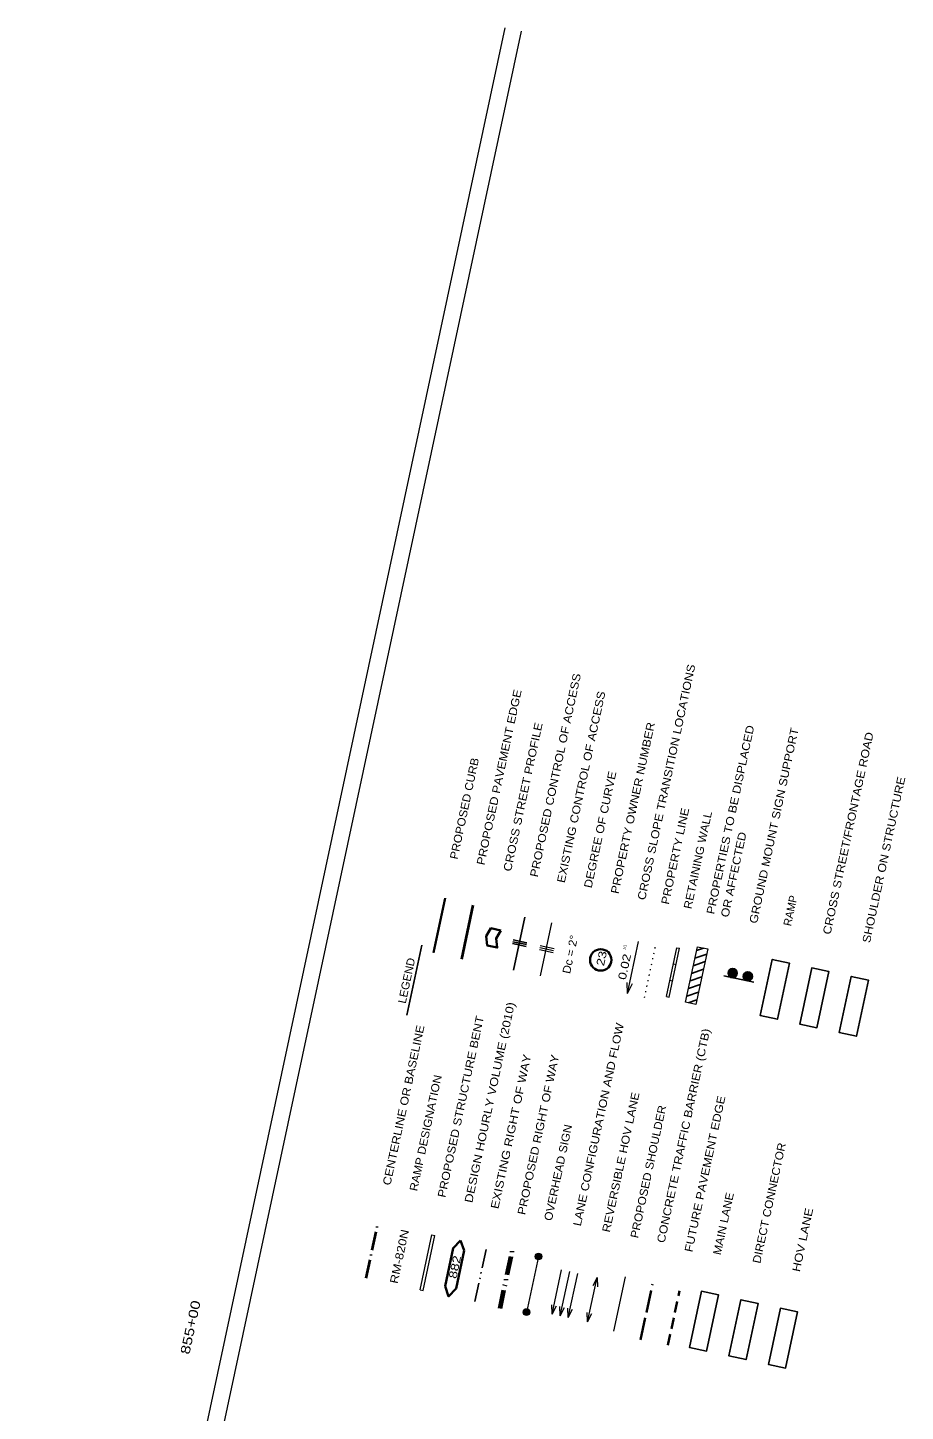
# Model space of a CAD drawing. Extents: x 2363411 to 2369702, y 6977197 to 6988655.
# Drawn here: x 2368386 to 2369702, y 6985397 to 6987471 of the extents above; entities that cross this region are included whole.
import ezdxf
from ezdxf.enums import TextEntityAlignment as Align

# ---------------------------------------------------------------- set-up
doc = ezdxf.new("R2010")
doc.units = 0
doc.header["$LTSCALE"] = 5.6
for name, pattern in [('DASH_DOUBLE_DOT', [9.2, 5, -1.2, 0.3, -1.2, 0.3, -1.2]), ('DOT_DASHED', [7.7, 5, -1.2, 0.3, -1.2]), ('DOTTED', [1.5, 0.3, -1.2]), ('LONG_DASHED', [7.5, 6, -1.5]), ('MEDIUM_DASHED', [4.5, 3, -1.5])]:
    doc.linetypes.add(name, pattern=pattern)
for name, color, linetype, lineweight in [('10', 7, 'Continuous', 13), ('2', 7, 'LONG_DASHED', 35), ('3', 7, 'Continuous', 13), ('44', 7, 'Continuous', 25), ('62', 7, 'Continuous', 25), ('7', 7, 'Continuous', 25)]:
    doc.layers.add(name, color=color, linetype=linetype, lineweight=lineweight)

msp = doc.modelspace()

# ---------------------------------------------------------------- hatches: boundary and pattern name
at = {"layer": '3'}
for points in [[(2369444.466, 6986060.545, 1), (2369441.566, 6986046.971, 1)], [(2369467.219, 6986055.682, 1), (2369464.319, 6986042.109, 1)], [(2369152.887, 6985633.803, 1), (2369150.797, 6985624.023, 1)], [(2369134.988, 6985550.401, 1), (2369132.898, 6985540.621, 1)]]:
    msp.add_hatch(color=256, dxfattribs=at).paths.add_polyline_path(points)

# ---------------------------------------------------------------- linework, layer by layer
at = {"layer": '10'}
for p, q in [((2366907.66, 6977202.711), (2369101.754, 6987471.397)), ((2366932.108, 6977197.487), (2369126.202, 6987466.173))]:
    msp.add_line(p, q, dxfattribs=at)
at = {"layer": '2'}
msp.add_line((2369304.647, 6985503.886), (2369322.798, 6985587.217), dxfattribs=at)
at = {"layer": '3'}
for p, q in [((2368993.928, 6986084.651), (2369011.385, 6986166.351)), ((2368995.395, 6986084.338), (2369012.852, 6986166.037)), ((2369011.224, 6986165.598), (2369011.065, 6986164.855)), ((2369155.018, 6986049.597), (2369171.992, 6986129.038)), ((2369153.188, 6986089.226), (2369173.89, 6986084.803)), ((2369153.815, 6986092.16), (2369174.517, 6986087.737)), ((2369154.441, 6986095.094), (2369175.144, 6986090.671)), ((2369285.259, 6986023.088), (2369301.964, 6986101.267)), ((2369343.667, 6986018.533), (2369359.311, 6986091.885)), ((2369347.588, 6986017.695), (2369363.235, 6986091.047)), ((2369359.327, 6986091.882), (2369363.251, 6986091.046)), ((2369354.113, 6986067.432), (2369358.034, 6986066.594)), ((2369348.895, 6986042.98), (2369352.817, 6986042.144)), ((2369285.259, 6986023.088), (2369284.606, 6986039.65)), ((2369285.259, 6986023.088), (2369292.625, 6986037.937)), ((2369343.678, 6986018.529), (2369347.6, 6986017.693)), ((2368974.484, 6985578.751), (2368992.1, 6985661.194)), ((2368978.983, 6985577.789), (2368996.598, 6985660.233)), ((2368992.1, 6985661.194), (2368996.598, 6985660.233)), ((2369151.843, 6985628.913), (2369133.905, 6985544.963)), ((2369172.363, 6985542.24), (2369186.562, 6985608.692)), ((2369184.413, 6985539.665), (2369198.612, 6985606.117)), ((2369196.461, 6985537.091), (2369210.66, 6985603.543)), ((2369239.737, 6985597.33), (2369240.288, 6985583.254)), ((2369264.741, 6985516.638), (2369282.197, 6985598.338)), ((2368974.484, 6985578.751), (2368978.983, 6985577.789)), ((2369172.363, 6985542.24), (2369171.812, 6985556.315)), ((2369172.363, 6985542.24), (2369178.618, 6985554.861)), ((2369184.413, 6985539.665), (2369183.862, 6985553.741)), ((2369184.413, 6985539.665), (2369190.668, 6985552.286)), ((2369196.461, 6985537.091), (2369195.91, 6985551.166)), ((2369196.461, 6985537.091), (2369202.717, 6985549.712)), ((2369225.539, 6985530.878), (2369224.988, 6985544.953)), ((2369225.539, 6985530.878), (2369231.794, 6985543.499))]:
    msp.add_line(p, q, dxfattribs=at)
at = {"layer": '3', "lineweight": 40}
msp.add_line((2369053.568, 6986155.773), (2369036.272, 6986074.826), dxfattribs=at)
at = {"layer": '3', "lineweight": 25}
for p, q in [((2369114.459, 6986058.263), (2369131.433, 6986137.704)), ((2369113.883, 6986103.76), (2369134.586, 6986099.337)), ((2368954.477, 6985990.905), (2368976.84, 6986095.567)), ((2369112.629, 6986097.893), (2369133.332, 6986093.469)), ((2369113.256, 6986100.826), (2369133.959, 6986096.403)), ((2369429.96, 6986049.577), (2369474.988, 6986039.956))]:
    msp.add_line(p, q, dxfattribs=at)
at = {"layer": '3', "linetype": 'DOTTED'}
msp.add_line((2369310.841, 6986016.937), (2369328.297, 6986098.637), dxfattribs=at)
at = {"layer": '3', "linetype": 'DOT_DASHED', "lineweight": 40}
msp.add_line((2368893.398, 6985596.199), (2368911.028, 6985678.71), dxfattribs=at)
at = {"layer": '3', "lineweight": 35}
for p, q in [((2369040.317, 6985637.557), (2369035.017, 6985652.811)), ((2369028.143, 6985580.581), (2369040.317, 6985637.557))]:
    msp.add_line(p, q, dxfattribs=at)
at = {"layer": '3', "linetype": 'DASH_DOUBLE_DOT', "lineweight": 25}
msp.add_line((2369056.542, 6985561.34), (2369074.172, 6985643.852), dxfattribs=at)
at = {"layer": '3', "linetype": 'DASH_DOUBLE_DOT', "lineweight": 70}
msp.add_line((2369094.114, 6985550.96), (2369113.14, 6985640.004), dxfattribs=at)
at = {"layer": '3', "linetype": 'MEDIUM_DASHED', "lineweight": 35}
msp.add_line((2369345.982, 6985495.732), (2369363.438, 6985577.432), dxfattribs=at)
at = {"layer": '3', "lineweight": 35}
msp.add_lwpolyline([(2369095.512, 6986117.707), (2369088.32, 6986105.776), (2369090.01, 6986091.956), (2369075.086, 6986095.145), (2369073.397, 6986108.965), (2369080.588, 6986120.895)], close=True, dxfattribs=at)
for points in [[(2369011.645, 6985584.106), (2369023.819, 6985641.082), (2369035.017, 6985652.811)], [(2369011.645, 6985584.106), (2369017.08, 6985568.862), (2369028.143, 6985580.581)]]:
    msp.add_lwpolyline(points, dxfattribs=at)
at = {"layer": '3'}
msp.add_lwpolyline([(2369225.539, 6985530.878), (2369239.737, 6985597.33), (2369233.482, 6985584.708)], dxfattribs=at)
at = {"layer": '3', "lineweight": 35}
msp.add_circle((2369245.233, 6986073.549), 16.098, dxfattribs=at)
at = {"layer": '3', "lineweight": 25}
for centre in [(2369443.016, 6986053.758), (2369465.769, 6986048.895)]:
    msp.add_circle(centre, 6.94, dxfattribs=at)
at = {"layer": '3'}
for centre in [(2369151.842, 6985628.913), (2369133.943, 6985545.511)]:
    msp.add_circle(centre, 5, dxfattribs=at)
at = {"layer": '62'}
for points in [[(2369484.449, 6985989.992), (2369502.442, 6986074.202), (2369528.183, 6986068.702), (2369510.19, 6985984.492)], [(2369510.19, 6985984.492), (2369528.183, 6986068.702), (2369502.442, 6986074.202), (2369484.449, 6985989.992)], [(2369543.686, 6985977.335), (2369561.679, 6986061.544), (2369587.418, 6986056.045), (2369569.425, 6985971.836)], [(2369569.425, 6985971.836), (2369587.418, 6986056.045), (2369561.679, 6986061.544), (2369543.686, 6985977.335)], [(2369602.921, 6985964.679), (2369620.914, 6986048.888), (2369646.655, 6986043.388), (2369628.662, 6985959.179)], [(2369628.662, 6985959.179), (2369646.655, 6986043.388), (2369620.914, 6986048.888), (2369602.921, 6985964.679)], [(2369378.131, 6985492.41), (2369396.124, 6985576.619), (2369421.865, 6985571.119), (2369403.872, 6985486.91)], [(2369403.872, 6985486.91), (2369421.865, 6985571.119), (2369396.124, 6985576.619), (2369378.131, 6985492.41)], [(2369437.368, 6985479.753), (2369455.361, 6985563.962), (2369481.1, 6985558.462), (2369463.107, 6985474.253)], [(2369463.107, 6985474.253), (2369481.1, 6985558.462), (2369455.361, 6985563.962), (2369437.368, 6985479.753)], [(2369496.603, 6985467.096), (2369514.596, 6985551.305), (2369540.337, 6985545.805), (2369522.344, 6985461.596)], [(2369522.344, 6985461.596), (2369540.337, 6985545.805), (2369514.596, 6985551.305), (2369496.603, 6985467.096)]]:
    msp.add_lwpolyline(points, close=True, dxfattribs=at)
at = {"layer": '7'}
for p, q in [((2369386.437, 6986076.24), (2369404.094, 6986082.38)), ((2369388.877, 6986087.677), (2369399.413, 6986091.34)), ((2369383.995, 6986064.804), (2369401.652, 6986070.944)), ((2369379.112, 6986041.931), (2369396.767, 6986048.07)), ((2369381.554, 6986053.365), (2369399.208, 6986059.506)), ((2369374.231, 6986019.058), (2369391.883, 6986025.195)), ((2369376.673, 6986030.494), (2369394.325, 6986036.633)), ((2369376.157, 6986009.139), (2369389.442, 6986013.759))]:
    msp.add_line(p, q, dxfattribs=at)
at = {"layer": '7', "lineweight": 13}
msp.add_lwpolyline([(2369387.919, 6986006.63), (2369372.29, 6986009.965), (2369390.085, 6986093.331), (2369405.718, 6986089.993)], close=True, dxfattribs=at)

# ---------------------------------------------------------------- texts
at = {"layer": '3'}
for s, width, p in [('PROPOSED CONTROL OF ACCESS', 1.15, (2369150.538, 6986196.87)), ('CROSS SLOPE TRANSITION LOCATIONS', 1.15, (2369311.807, 6986162.412)), ('PROPOSED PAVEMENT EDGE', 1.15, (2369070.573, 6986214.877)), ('EXISTING CONTROL OF ACCESS', 1.15, (2369191.096, 6986188.204)), ('CROSS STREET PROFILE', 1.15, (2369110.629, 6986205.398)), ('PROPERTY OWNER NUMBER', 1.15, (2369271.749, 6986171.83)), ('PROPERTIES TO BE DISPLACED', 1.15, (2369415.273, 6986141.164)), ('GROUND MOUNT SIGN SUPPORT', 1.15, (2369479.534, 6986127.239)), ('PROPOSED CURB', 1.1, (2369030.352, 6986223.532)), ('DEGREE OF CURVE', 1.15, (2369231.506, 6986180.429)), ('PROPERTY LINE', 1.15, (2369347.264, 6986155.818)), ('RETAINING WALL', 1.1, (2369381.08, 6986149.096)), ('OR AFFECTED', 1.15, (2369436.788, 6986136.567)), ('Dc = 2°', 1.1, (2369199.119, 6986051.924)), ('23', 1.25, (2369249.958, 6986063.621)), ('0.02', 1.25, (2369282.645, 6986042.871)), ('LEGEND', 1.05, (2368952.631, 6986007.344)), ('DESIGN HOURLY VOLUME (2010)', 1.2, (2369052.438, 6985708.453)), ('PROPOSED STRUCTURE BENT', 1.15, (2369012.055, 6985716.397)), ('LANE CONFIGURATION AND FLOW', 1.15, (2369215.187, 6985673.546)), ('CENTERLINE OR BASELINE', 1.15, (2368929.754, 6985734.667)), ('CONCRETE TRAFFIC BARRIER (CTB)', 1.15, (2369340.939, 6985648.318)), ('EXISTING RIGHT OF WAY', 1.2, (2369091.61, 6985699.337)), ('PROPOSED RIGHT OF WAY', 1.15, (2369131.769, 6985690.388)), ('RAMP DESIGNATION', 1.1, (2368969.869, 6985726.034)), ('REVERSIBLE HOV LANE', 1.15, (2369258.767, 6985664.234)), ('PROPOSED SHOULDER', 1.1, (2369301.164, 6985655.52)), ('FUTURE PAVEMENT EDGE', 1.15, (2369382.404, 6985634.614)), ('OVERHEAD SIGN', 1.1, (2369171.742, 6985681.471)), ('RM-820N', 1.2, (2368940.437, 6985587.283)), ('882', 1.3, (2369028.628, 6985594.671))]:
    msp.add_text(s, height=12, rotation=77.939, dxfattribs=dict(at, width=width)).set_placement(p)
msp.add_text('1/1', height=4.18, rotation=77.939, dxfattribs=at).set_placement((2369282.29, 6986088.167))
at = {"layer": '44', "width": 1.3}
msp.add_text('855+00', height=14, rotation=77.939, dxfattribs=at).set_placement((2368636.7, 6985521.132), align=Align.CENTER)
at = {"layer": '62'}
for s, width, p in [('CROSS STREET/FRONTAGE ROAD', 1.15, (2369589.838, 6986110.8)), ('SHOULDER ON STRUCTURE', 1.15, (2369649.075, 6986098.143)), ('DIRECT CONNECTOR', 1.1, (2369484.468, 6985617.649)), ('MAIN LANE', 1.1, (2369425.233, 6985630.306)), ('HOV LANE', 1.2, (2369543.704, 6985604.992))]:
    msp.add_text(s, height=12, rotation=77.939, dxfattribs=dict(at, width=width)).set_placement(p)
msp.add_text('RAMP', height=12, rotation=77.939, dxfattribs=at).set_placement((2369530.603, 6986123.456))

doc.saveas('drawing.dxf')
